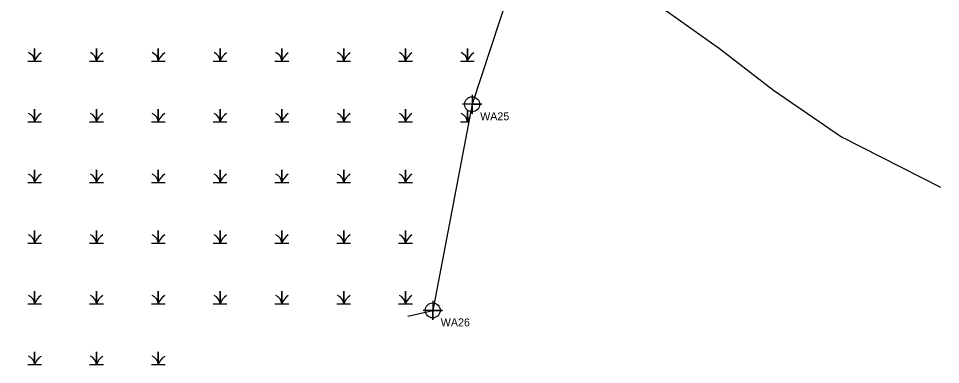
# Model space of a CAD drawing. Extents: x 2603618 to 2605510, y 618189 to 619022.
# Drawn here: x 2603915.3 to 2604203.3, y 618245.1 to 618353.1 of the extents above; entities that cross this region are included whole.
import ezdxf

# ---------------------------------------------------------------- set-up
doc = ezdxf.new("R2010")
doc.units = 0
for name, color, linetype in [('Exist Environmental Wetland Boundary', 7, 'Continuous'), ('Exist Environmental Wetland Boundary Cogo Comment', 7, 'Continuous'), ('Exist Environmental Wetland Boundary Cogo Point CELL', 7, 'Continuous'), ('Exist Hydro Jurisdictional Stream or Body of Water Mitigable', 7, 'Continuous')]:
    doc.layers.add(name, color=color, linetype=linetype)

msp = doc.modelspace()

# ---------------------------------------------------------------- linework, layer by layer
at = {"layer": 'Exist Environmental Wetland Boundary'}
msp.add_line((2604036.94, 618260.17), (2604044.69, 618262), dxfattribs=at)
for points in [[(2603897.92, 618497.01), (2603938.9, 618484.11), (2603982.11, 618484.31), (2604015.8, 618458.6), (2604068.49, 618361.23), (2604056.99, 618326.31), (2604044.69, 618262)], [(2603918.23, 618339.82), (2603920.38, 618339.82), (2603920.38, 618343.76), (2603920.38, 618339.82), (2603922.53, 618339.82)], [(2603937.53, 618339.82), (2603939.68, 618339.82), (2603939.68, 618343.76), (2603939.68, 618339.82), (2603941.83, 618339.82)], [(2603956.83, 618339.82), (2603958.98, 618339.82), (2603958.98, 618343.76), (2603958.98, 618339.82), (2603961.13, 618339.82)], [(2603976.13, 618339.82), (2603978.28, 618339.82), (2603978.28, 618343.76), (2603978.28, 618339.82), (2603980.43, 618339.82)], [(2603995.43, 618339.82), (2603997.58, 618339.82), (2603997.58, 618343.76), (2603997.58, 618339.82), (2603999.73, 618339.82)], [(2604014.73, 618339.82), (2604016.88, 618339.82), (2604016.88, 618343.76), (2604016.88, 618339.82), (2604019.04, 618339.82)], [(2604034.04, 618339.82), (2604036.19, 618339.82), (2604036.19, 618343.76), (2604036.19, 618339.82), (2604038.34, 618339.82)], [(2604053.34, 618339.82), (2604055.49, 618339.82), (2604055.49, 618343.76), (2604055.49, 618339.82), (2604057.64, 618339.82)], [(2603918.23, 618320.87), (2603920.38, 618320.87), (2603920.38, 618324.82), (2603920.38, 618320.87), (2603922.53, 618320.87)], [(2603937.53, 618320.87), (2603939.68, 618320.87), (2603939.68, 618324.82), (2603939.68, 618320.87), (2603941.83, 618320.87)], [(2603956.83, 618320.87), (2603958.98, 618320.87), (2603958.98, 618324.82), (2603958.98, 618320.87), (2603961.13, 618320.87)], [(2603976.13, 618320.87), (2603978.28, 618320.87), (2603978.28, 618324.82), (2603978.28, 618320.87), (2603980.43, 618320.87)], [(2603995.43, 618320.87), (2603997.58, 618320.87), (2603997.58, 618324.82), (2603997.58, 618320.87), (2603999.73, 618320.87)], [(2604014.73, 618320.87), (2604016.88, 618320.87), (2604016.88, 618324.82), (2604016.88, 618320.87), (2604019.04, 618320.87)], [(2604034.04, 618320.87), (2604036.19, 618320.87), (2604036.19, 618324.82), (2604036.19, 618320.87), (2604038.34, 618320.87)], [(2604053.34, 618320.87), (2604055.49, 618320.87), (2604055.49, 618324.51)], [(2604055.49, 618324.51), (2604055.49, 618320.87), (2604055.95, 618320.87)], [(2603918.23, 618301.93), (2603920.38, 618301.93), (2603920.38, 618305.87), (2603920.38, 618301.93), (2603922.53, 618301.93)], [(2603937.53, 618301.93), (2603939.68, 618301.93), (2603939.68, 618305.87), (2603939.68, 618301.93), (2603941.83, 618301.93)], [(2603956.83, 618301.93), (2603958.98, 618301.93), (2603958.98, 618305.87), (2603958.98, 618301.93), (2603961.13, 618301.93)], [(2603976.13, 618301.93), (2603978.28, 618301.93), (2603978.28, 618305.87), (2603978.28, 618301.93), (2603980.43, 618301.93)], [(2603995.43, 618301.93), (2603997.58, 618301.93), (2603997.58, 618305.87), (2603997.58, 618301.93), (2603999.73, 618301.93)], [(2604014.73, 618301.93), (2604016.88, 618301.93), (2604016.88, 618305.87), (2604016.88, 618301.93), (2604019.04, 618301.93)], [(2604034.04, 618301.93), (2604036.19, 618301.93), (2604036.19, 618305.87), (2604036.19, 618301.93), (2604038.34, 618301.93)], [(2603918.23, 618282.98), (2603920.38, 618282.98), (2603920.38, 618286.93), (2603920.38, 618282.98), (2603922.53, 618282.98)], [(2603937.53, 618282.98), (2603939.68, 618282.98), (2603939.68, 618286.93), (2603939.68, 618282.98), (2603941.83, 618282.98)], [(2603956.83, 618282.98), (2603958.98, 618282.98), (2603958.98, 618286.93), (2603958.98, 618282.98), (2603961.13, 618282.98)], [(2603976.13, 618282.98), (2603978.28, 618282.98), (2603978.28, 618286.93), (2603978.28, 618282.98), (2603980.43, 618282.98)], [(2603995.43, 618282.98), (2603997.58, 618282.98), (2603997.58, 618286.93), (2603997.58, 618282.98), (2603999.73, 618282.98)], [(2604014.73, 618282.98), (2604016.88, 618282.98), (2604016.88, 618286.93), (2604016.88, 618282.98), (2604019.04, 618282.98)], [(2604034.04, 618282.98), (2604036.19, 618282.98), (2604036.19, 618286.93), (2604036.19, 618282.98), (2604038.34, 618282.98)], [(2603918.23, 618264.04), (2603920.38, 618264.04), (2603920.38, 618267.98), (2603920.38, 618264.04), (2603922.53, 618264.04)], [(2603937.53, 618264.04), (2603939.68, 618264.04), (2603939.68, 618267.98), (2603939.68, 618264.04), (2603941.83, 618264.04)], [(2603956.83, 618264.04), (2603958.98, 618264.04), (2603958.98, 618267.98), (2603958.98, 618264.04), (2603961.13, 618264.04)], [(2603976.13, 618264.04), (2603978.28, 618264.04), (2603978.28, 618267.98), (2603978.28, 618264.04), (2603980.43, 618264.04)], [(2603995.43, 618264.04), (2603997.58, 618264.04), (2603997.58, 618267.98), (2603997.58, 618264.04), (2603999.73, 618264.04)], [(2604014.73, 618264.04), (2604016.88, 618264.04), (2604016.88, 618267.98), (2604016.88, 618264.04), (2604019.04, 618264.04)], [(2604034.04, 618264.04), (2604036.19, 618264.04), (2604036.19, 618267.98), (2604036.19, 618264.04), (2604038.34, 618264.04)], [(2603918.23, 618245.09), (2603920.38, 618245.09), (2603920.38, 618249.04), (2603920.38, 618245.09), (2603922.53, 618245.09)], [(2603937.53, 618245.09), (2603939.68, 618245.09), (2603939.68, 618249.04), (2603939.68, 618245.09), (2603941.83, 618245.09)], [(2603956.83, 618245.09), (2603958.98, 618245.09), (2603958.98, 618249.04), (2603958.98, 618245.09), (2603961.13, 618245.09)]]:
    msp.add_lwpolyline(points, dxfattribs=at)
for centre, radius, start, end in [((2603917.31, 618339.6), 3.07, 4.1403, 67.535), ((2603924.94, 618338.3), 4.81, 122.1274, 161.6222), ((2603936.62, 618339.6), 3.07, 4.1403, 67.535), ((2603944.24, 618338.3), 4.81, 122.1274, 161.6222), ((2603955.92, 618339.6), 3.07, 4.1403, 67.535), ((2603963.54, 618338.3), 4.81, 122.1274, 161.6222), ((2603975.22, 618339.6), 3.07, 4.1403, 67.535), ((2603982.84, 618338.3), 4.81, 122.1274, 161.6222), ((2603994.52, 618339.6), 3.07, 4.1403, 67.535), ((2604002.14, 618338.3), 4.81, 122.1274, 161.6222), ((2604013.82, 618339.6), 3.07, 4.1403, 67.535), ((2604021.45, 618338.3), 4.81, 122.1274, 161.6222), ((2604033.12, 618339.6), 3.07, 4.1403, 67.535), ((2604040.75, 618338.3), 4.81, 122.1274, 161.6222), ((2604052.42, 618339.6), 3.07, 4.1403, 67.535), ((2604060.05, 618338.3), 4.81, 122.1274, 161.6222), ((2603917.31, 618320.65), 3.07, 4.1403, 67.535), ((2603924.94, 618319.36), 4.81, 122.1274, 161.6222), ((2603936.62, 618320.65), 3.07, 4.1403, 67.535), ((2603944.24, 618319.36), 4.81, 122.1274, 161.6222), ((2603955.92, 618320.65), 3.07, 4.1403, 67.535), ((2603963.54, 618319.36), 4.81, 122.1274, 161.6222), ((2603975.22, 618320.65), 3.07, 4.1403, 67.535), ((2603982.84, 618319.36), 4.81, 122.1274, 161.6222), ((2603994.52, 618320.65), 3.07, 4.1403, 67.535), ((2604002.14, 618319.36), 4.81, 122.1274, 161.6222), ((2604013.82, 618320.65), 3.07, 4.1403, 67.535), ((2604021.45, 618319.36), 4.81, 122.1274, 161.6222), ((2604033.12, 618320.65), 3.07, 4.1403, 67.535), ((2604040.75, 618319.36), 4.81, 122.1274, 161.6222), ((2604052.42, 618320.65), 3.07, 4.1403, 67.535), ((2604060.05, 618319.36), 4.81, 142.9702, 161.6222), ((2603917.31, 618301.71), 3.07, 4.1403, 67.535), ((2603924.94, 618300.41), 4.81, 122.1274, 161.6222), ((2603936.62, 618301.71), 3.07, 4.1403, 67.535), ((2603944.24, 618300.41), 4.81, 122.1274, 161.6222), ((2603955.92, 618301.71), 3.07, 4.1403, 67.535), ((2603963.54, 618300.41), 4.81, 122.1274, 161.6222), ((2603975.22, 618301.71), 3.07, 4.1403, 67.535), ((2603982.84, 618300.41), 4.81, 122.1274, 161.6222), ((2603994.52, 618301.71), 3.07, 4.1403, 67.535), ((2604002.14, 618300.41), 4.81, 122.1274, 161.6222), ((2604013.82, 618301.71), 3.07, 4.1403, 67.535), ((2604021.45, 618300.41), 4.81, 122.1274, 161.6222), ((2604033.12, 618301.71), 3.07, 4.1403, 67.535), ((2604040.75, 618300.41), 4.81, 122.1274, 161.6222), ((2603917.31, 618282.76), 3.07, 4.1403, 67.535), ((2603924.94, 618281.47), 4.81, 122.1274, 161.6222), ((2603936.62, 618282.76), 3.07, 4.1403, 67.535), ((2603944.24, 618281.47), 4.81, 122.1274, 161.6222), ((2603955.92, 618282.76), 3.07, 4.1403, 67.535), ((2603963.54, 618281.47), 4.81, 122.1274, 161.6222), ((2603975.22, 618282.76), 3.07, 4.1403, 67.535), ((2603982.84, 618281.47), 4.81, 122.1274, 161.6222), ((2603994.52, 618282.76), 3.07, 4.1403, 67.535), ((2604002.14, 618281.47), 4.81, 122.1274, 161.6222), ((2604013.82, 618282.76), 3.07, 4.1403, 67.535), ((2604021.45, 618281.47), 4.81, 122.1274, 161.6222), ((2604033.12, 618282.76), 3.07, 4.1403, 67.535), ((2604040.75, 618281.47), 4.81, 122.1274, 161.6222), ((2603917.31, 618263.82), 3.07, 4.1403, 67.535), ((2603924.94, 618262.52), 4.81, 122.1274, 161.6222), ((2603936.62, 618263.82), 3.07, 4.1403, 67.535), ((2603944.24, 618262.52), 4.81, 122.1274, 161.6222), ((2603955.92, 618263.82), 3.07, 4.1403, 67.535), ((2603963.54, 618262.52), 4.81, 122.1274, 161.6222), ((2603975.22, 618263.82), 3.07, 4.1403, 67.535), ((2603982.84, 618262.52), 4.81, 122.1274, 161.6222), ((2603994.52, 618263.82), 3.07, 4.1403, 67.535), ((2604002.14, 618262.52), 4.81, 122.1274, 161.6222), ((2604013.82, 618263.82), 3.07, 4.1403, 67.535), ((2604021.45, 618262.52), 4.81, 122.1274, 161.6222), ((2604033.12, 618263.82), 3.07, 4.1403, 67.535), ((2604040.75, 618262.52), 4.81, 122.1274, 161.6222), ((2603917.31, 618244.87), 3.07, 4.1403, 67.535), ((2603924.94, 618243.58), 4.81, 122.1274, 161.6222), ((2603936.62, 618244.87), 3.07, 4.1403, 67.535), ((2603944.24, 618243.58), 4.81, 122.1274, 161.6222), ((2603955.92, 618244.87), 3.07, 4.1403, 67.535), ((2603963.54, 618243.58), 4.81, 122.1274, 161.6188)]:
    msp.add_arc(centre, radius, start, end, dxfattribs=at)
at = {"layer": 'Exist Environmental Wetland Boundary Cogo Point CELL'}
for points in [[(2604056.99, 618329.31), (2604056.99, 618323.31), (2604056.99, 618326.31), (2604059.99, 618326.31), (2604053.99, 618326.31)], [(2604044.69, 618265), (2604044.69, 618259), (2604044.69, 618262), (2604047.69, 618262), (2604041.69, 618262)]]:
    msp.add_lwpolyline(points, dxfattribs=at)
for centre in [(2604056.99, 618326.31), (2604044.69, 618262)]:
    msp.add_circle(centre, 2.34, dxfattribs=at)
at = {"layer": 'Exist Hydro Jurisdictional Stream or Body of Water Mitigable'}
for points in [[(2604103.98, 618370.25), (2604114.88, 618357.43), (2604134.24, 618343.76), (2604151.09, 618330.77)], [(2604151.09, 618330.77), (2604172.28, 618316.18), (2604203.26, 618300.46)]]:
    msp.add_lwpolyline(points, dxfattribs=at)

# ---------------------------------------------------------------- texts
at = {"layer": 'Exist Environmental Wetland Boundary Cogo Comment'}
for s, p in [('WA25', (2604059.49, 618321.31)), ('WA26', (2604047.19, 618257))]:
    msp.add_text(s, height=2.5, dxfattribs=at).set_placement(p)

doc.saveas('drawing.dxf')
